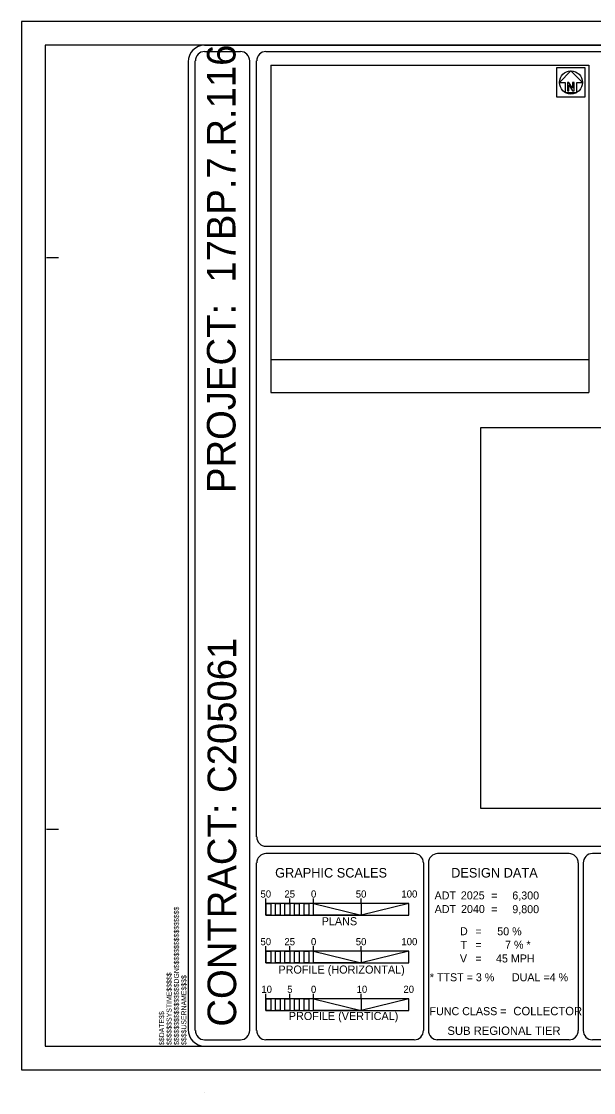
# Model space of a CAD drawing. Extents: x 2538775 to 2540487, y 826823 to 827953.
# Drawn here: x 2538775 to 2539375, y 826823 to 827947 of the extents above; entities that cross this region are included whole.
import ezdxf

# ---------------------------------------------------------------- set-up
doc = ezdxf.new("R2010")
doc.units = 0
for name, color, linetype in [('Old_Level_1', 7, 'Continuous'), ('Old_Level_10', 7, 'Continuous'), ('Old_Level_40', 7, 'Continuous'), ('Old_Level_41', 7, 'Continuous'), ('Old_Level_62', 7, 'Continuous'), ('Old_Level_63', 7, 'Continuous'), ('Sheet Data Field CELL', 7, 'Continuous')]:
    doc.layers.add(name, color=color, linetype=linetype)

msp = doc.modelspace()

# ---------------------------------------------------------------- linework, layer by layer
at = {"layer": 'Old_Level_1'}
msp.add_line((2538967, 826823.1), (2538967, 826823.1), dxfattribs=at)
msp.add_lwpolyline([(2539256.9, 827520.8), (2540207.7, 827520.8), (2540207.7, 827121.2), (2539256.9, 827121.2)], close=True, dxfattribs=at)
at = {"layer": 'Old_Level_10'}
for p, q in [((2539351.6, 827895.1), (2539339.6, 827882.8)), ((2539363.7, 827882.8), (2539351.6, 827895.1)), ((2539339.6, 827882.8), (2539345.6, 827882.8)), ((2539345.6, 827882.8), (2539345.6, 827872.2)), ((2539357.7, 827872.2), (2539357.7, 827882.8)), ((2539357.7, 827882.8), (2539363.7, 827882.8)), ((2539345.6, 827872.2), (2539357.7, 827872.2))]:
    msp.add_line(p, q, dxfattribs=at)
for points in [[(2539336.6, 827867.6), (2539366.7, 827867.6), (2539366.7, 827898.1), (2539336.6, 827898.1)], [(2539348, 827882.8), (2539348, 827874.2), (2539349.6, 827874.2), (2539349.6, 827880.2), (2539353.2, 827874.2), (2539354.9, 827874.2), (2539354.9, 827882.8), (2539353.2, 827882.8), (2539353.2, 827876.8), (2539349.6, 827882.8)]]:
    msp.add_lwpolyline(points, close=True, dxfattribs=at)
msp.add_ellipse((2539351.6, 827882.8), major_axis=(0, 12.2), ratio=0.985213, dxfattribs=at)
at = {"layer": 'Old_Level_40'}
for p, q in [((2538957.4, 827398.3), (2538957.4, 827905.4)), ((2539014.5, 827398.1), (2539014.5, 827905.4)), ((2539021.8, 827398.1), (2539021.8, 827905.4)), ((2539036.8, 827900.9), (2539370.3, 827900.9)), ((2539036.8, 827900.9), (2539036.8, 827557.5)), ((2539370.3, 827900.9), (2539370.3, 827557.5)), ((2539036.8, 827592), (2539370.3, 827592)), ((2539036.8, 827557.5), (2539370.3, 827557.5)), ((2538957.4, 826888.3), (2538957.4, 827398.3)), ((2539014.5, 826888.3), (2539014.5, 827398.1)), ((2539021.8, 827091.3), (2539021.8, 827398.1)), ((2540433.1, 827081.4), (2539031.5, 827081.4)), ((2539187.2, 827073.8), (2539031.5, 827073.8)), ((2539349.7, 827073.8), (2539211.7, 827073.8)), ((2539704.9, 827073.8), (2539374.2, 827073.8)), ((2539021.8, 826888.3), (2539021.8, 827064)), ((2539196.8, 827064), (2539196.8, 826888.3)), ((2539202, 827064), (2539202, 826888.3)), ((2539359.3, 827064), (2539359.3, 826888.3)), ((2539364.6, 827064), (2539364.6, 826888.3)), ((2539031.5, 827021.6), (2539031.5, 827026.6)), ((2539031.5, 827026.6), (2539031.5, 827026.6)), ((2539056.5, 827021.6), (2539056.5, 827026.6)), ((2539081.5, 827021.6), (2539081.5, 827026.6)), ((2539131.5, 827021.6), (2539131.5, 827026.6)), ((2539031.5, 827021.6), (2539031.5, 827009.1)), ((2539031.5, 827021.6), (2539031.5, 827021.6)), ((2539181.5, 827021.6), (2539031.5, 827021.6)), ((2539066.5, 827021.6), (2539066.5, 827009.1)), ((2539131.5, 827021.6), (2539131.5, 827009.1)), ((2539031.5, 827009.1), (2539181.5, 827009.1)), ((2539031.5, 826971.6), (2539031.5, 826976.6)), ((2539031.5, 826971.6), (2539031.5, 826976.6)), ((2539031.5, 826976.6), (2539031.5, 826976.6)), ((2539031.5, 826971.6), (2539031.5, 826959.1)), ((2539031.5, 826971.6), (2539031.5, 826971.6)), ((2539181.5, 826971.6), (2539031.5, 826971.6)), ((2539031.5, 826971.6), (2539031.5, 826971.6)), ((2539181.5, 826971.6), (2539031.5, 826971.6)), ((2539056.5, 826971.6), (2539056.5, 826976.6)), ((2539056.5, 826971.6), (2539056.5, 826976.6)), ((2539066.5, 826971.6), (2539066.5, 826959.1)), ((2539081.5, 826971.6), (2539081.5, 826976.6)), ((2539081.5, 826971.6), (2539081.5, 826976.6)), ((2539131.5, 826971.6), (2539131.5, 826976.6)), ((2539131.5, 826971.6), (2539131.5, 826976.6)), ((2539131.5, 826971.6), (2539131.5, 826959.1)), ((2539031.5, 826959.1), (2539181.5, 826959.1)), ((2539031.5, 826921.6), (2539031.5, 826926.6)), ((2539031.5, 826921.6), (2539031.5, 826926.6)), ((2539031.5, 826921.6), (2539031.5, 826926.6)), ((2539031.5, 826926.6), (2539031.5, 826926.6)), ((2539056.5, 826921.6), (2539056.5, 826926.6)), ((2539056.5, 826921.6), (2539056.5, 826926.6)), ((2539056.5, 826921.6), (2539056.5, 826926.6)), ((2539081.5, 826921.6), (2539081.5, 826926.6)), ((2539081.5, 826921.6), (2539081.5, 826926.6)), ((2539081.5, 826921.6), (2539081.5, 826926.6)), ((2539131.5, 826921.6), (2539131.5, 826926.6)), ((2539131.5, 826921.6), (2539131.5, 826926.6)), ((2539131.5, 826921.6), (2539131.5, 826926.6)), ((2539031.5, 826921.6), (2539031.5, 826909.1)), ((2539031.5, 826921.6), (2539031.5, 826921.6)), ((2539181.5, 826921.6), (2539031.5, 826921.6)), ((2539031.5, 826921.6), (2539031.5, 826921.6)), ((2539181.5, 826921.6), (2539031.5, 826921.6)), ((2539031.5, 826921.6), (2539031.5, 826921.6)), ((2539181.5, 826921.6), (2539031.5, 826921.6)), ((2539066.5, 826921.6), (2539066.5, 826909.1)), ((2539131.5, 826921.6), (2539131.5, 826909.1)), ((2539031.5, 826909.1), (2539181.5, 826909.1)), ((2538967.1, 826878.5), (2539004.8, 826878.5)), ((2539187.2, 826878.5), (2539031.5, 826878.5)), ((2539349.7, 826878.5), (2539210.8, 826878.5)), ((2539704.9, 826878.5), (2539374.2, 826878.5))]:
    msp.add_line(p, q, dxfattribs=at)
for points in [[(2538967.1, 827921.8), (2540432.7, 827921.8)], [(2538967.1, 827915.2), (2539004.8, 827915.2)], [(2539031.5, 827915.2), (2540433.1, 827915.2)], [(2538949.9, 827904.4), (2538949.9, 827398.3)], [(2538949.9, 827398.3), (2538949.9, 826889.3)], [(2538967.1, 826871.8), (2540432.7, 826871.8)]]:
    msp.add_lwpolyline(points, dxfattribs=at)
for points in [[(2539031.5, 827021.6), (2539036.5, 827021.6), (2539036.5, 827009.1), (2539031.5, 827009.1)], [(2539041.5, 827021.6), (2539046.5, 827021.6), (2539046.5, 827009.1), (2539041.5, 827009.1)], [(2539051.5, 827021.6), (2539056.5, 827021.6), (2539056.5, 827009.1), (2539051.5, 827009.1)], [(2539061.5, 827021.6), (2539066.5, 827021.6), (2539066.5, 827009.1), (2539061.5, 827009.1)], [(2539071.5, 827021.6), (2539076.5, 827021.6), (2539076.5, 827009.1), (2539071.5, 827009.1)], [(2539081.5, 827021.6), (2539131.5, 827009.1), (2539081.5, 827009.1)], [(2539181.5, 827021.6), (2539131.5, 827009.1), (2539181.5, 827009.1)], [(2539031.5, 826971.6), (2539036.5, 826971.6), (2539036.5, 826959.1), (2539031.5, 826959.1)], [(2539041.5, 826971.6), (2539046.5, 826971.6), (2539046.5, 826959.1), (2539041.5, 826959.1)], [(2539051.5, 826971.6), (2539056.5, 826971.6), (2539056.5, 826959.1), (2539051.5, 826959.1)], [(2539061.5, 826971.6), (2539066.5, 826971.6), (2539066.5, 826959.1), (2539061.5, 826959.1)], [(2539071.5, 826971.6), (2539076.5, 826971.6), (2539076.5, 826959.1), (2539071.5, 826959.1)], [(2539081.5, 826971.6), (2539131.5, 826959.1), (2539081.5, 826959.1)], [(2539181.5, 826971.6), (2539131.5, 826959.1), (2539181.5, 826959.1)], [(2539031.5, 826921.6), (2539036.5, 826921.6), (2539036.5, 826909.1), (2539031.5, 826909.1)], [(2539041.5, 826921.6), (2539046.5, 826921.6), (2539046.5, 826909.1), (2539041.5, 826909.1)], [(2539051.5, 826921.6), (2539056.5, 826921.6), (2539056.5, 826909.1), (2539051.5, 826909.1)], [(2539061.5, 826921.6), (2539066.5, 826921.6), (2539066.5, 826909.1), (2539061.5, 826909.1)], [(2539071.5, 826921.6), (2539076.5, 826921.6), (2539076.5, 826909.1), (2539071.5, 826909.1)], [(2539081.5, 826921.6), (2539131.5, 826909.1), (2539081.5, 826909.1)], [(2539181.5, 826921.6), (2539131.5, 826909.1), (2539181.5, 826909.1)]]:
    msp.add_lwpolyline(points, close=True, dxfattribs=at)
for centre, major_axis, start_param, end_param in [((2538967.1, 827904.4), (0, 17.5), 6.283183, 7.853978), ((2538967.1, 827905.4), (0, 9.81), 6.283183, 7.853978), ((2539004.8, 827905.4), (0, 9.81), 4.712408, 6.283194), ((2539031.5, 827905.4), (0, -9.81), 3.141603, 4.712391), ((2539031.5, 827091.3), (0, -9.81), 4.712389, 6.283185), ((2539031.5, 827064), (0, -9.81), 3.141593, 4.712389), ((2539031.5, 827064), (0, 9.81), 0, 1.570796), ((2539187.2, 827064), (0, 9.81), 4.712389, 6.283185), ((2539211.7, 827064), (0, -9.81), 3.141593, 4.712389), ((2539349.7, 827064), (0, 9.81), 4.712389, 6.283185), ((2539374.2, 827064), (0, -9.81), 3.140818, 4.712389), ((2538967.1, 826889.3), (0, -17.5), 4.712389, 6.283185), ((2538967.1, 826888.3), (0, -9.81), 4.712389, 6.283185), ((2539004.8, 826888.3), (0, 9.81), 3.141593, 4.712389), ((2539031.5, 826888.3), (0, -9.81), 4.712389, 6.283185), ((2539187.2, 826888.3), (0, -9.81), 0, 1.570796), ((2539211.7, 826888.3), (0, -9.81), 4.712389, 6.283185), ((2539349.7, 826888.3), (0, -9.81), 0, 1.570796), ((2539374.2, 826888.3), (0, -9.81), 4.712389, 6.283185)]:
    msp.add_ellipse(centre, major_axis=major_axis, ratio=0.985213, start_param=start_param, end_param=end_param, dxfattribs=at)
at = {"layer": 'Old_Level_41'}
for p, q in [((2538801.4, 827699.3), (2538813.9, 827699.3)), ((2538801.4, 827099.3), (2538813.9, 827099.3))]:
    msp.add_line(p, q, dxfattribs=at)
at = {"layer": 'Old_Level_62'}
msp.add_lwpolyline([(2538799.9, 826871.8), (2540449.9, 826871.8), (2540449.9, 827921.8), (2538799.9, 827921.8)], close=True, dxfattribs=at)
at = {"layer": 'Old_Level_63'}
msp.add_lwpolyline([(2538774.9, 826846.8), (2540474.9, 826846.8), (2540474.9, 827946.8), (2538774.9, 827946.8)], close=True, dxfattribs=at)

# ---------------------------------------------------------------- texts
at = {"layer": 'Old_Level_40'}
for s, height, rotation, p in [('PROJECT:  17BP.7.R.116', 30, 90, (2538999.6, 827452.1)), ('CONTRACT: C205061', 30, 90, (2539000.3, 826892.3)), ('GRAPHIC SCALES', 10, 360, (2539041.2, 827048.7)), ('DESIGN DATA', 10.023, 360, (2539225.9, 827048.7)), ('50', 7.5, 360, (2539025.8, 827027.7)), ('25', 7.5, 360, (2539050.9, 827027.7)), ('0', 7.5, 360, (2539078.8, 827027.7)), ('50', 7.5, 360, (2539125.8, 827027.7)), ('100', 7.5, 360, (2539173.7, 827027.7)), ('PLANS', 8.5, 360, (2539090, 826998.6)), ('50', 7.5, 360, (2539025.8, 826977.7)), ('25', 7.5, 360, (2539050.9, 826977.7)), ('0', 7.5, 360, (2539078.8, 826977.7)), ('0', 7.5, 360, (2539078.8, 826977.6)), ('50', 7.5, 360, (2539125.8, 826977.7)), ('100', 7.5, 360, (2539173.7, 826977.7)), ('PROFILE (HORIZONTAL)', 8.5, 360, (2539044.6, 826947.9)), ('10', 7.5, 360, (2539026.7, 826927.7)), ('5', 7.5, 360, (2539053.9, 826927.7)), ('0', 7.5, 360, (2539078.8, 826927.7)), ('0', 7.5, 360, (2539078.8, 826927.6)), ('0', 7.5, 360, (2539078.8, 826927.6)), ('10', 7.5, 360, (2539126.7, 826927.7)), ('20', 7.5, 360, (2539175.8, 826927.7)), ('COLLECTOR', 8.83, 360, (2539291.2, 826904.2)), ('PROFILE (VERTICAL)', 8.5, 360, (2539055.5, 826899.2)), ('SUB REGIONAL TIER', 8.83, 360, (2539222, 826883.6))]:
    msp.add_text(s, height=height, rotation=rotation, dxfattribs=at).set_placement(p)
at = {"layer": 'Old_Level_41'}
for s, p in [('$$$$$$$$$$$$$$$$DGN$$$$$$$$$$$$$$$$', (2538940.2, 826873)), ('$$$$$$SYSTIME$$$$$', (2538932.5, 826873)), ('$$$$USERNAME$$$$', (2538948, 826873)), ('$$DATE$$', (2538924.7, 826873))]:
    msp.add_text(s, height=5.25, rotation=90, dxfattribs=at).set_placement(p)
at = {"layer": 'Sheet Data Field CELL'}
for s, p in [('ADT', (2539208.5, 827025.7)), ('2025', (2539236.1, 827025.8)), ('=', (2539268, 827025.7)), ('6,300', (2539290.1, 827025.7)), ('ADT', (2539208.6, 827011.4)), ('2040', (2539236.3, 827011.5)), ('=', (2539268, 827011.3)), ('9,800', (2539290.1, 827011.3)), ('D', (2539235.2, 826988.2)), ('=', (2539251.4, 826988.1)), ('50 %', (2539274.3, 826988.1)), ('T', (2539235.8, 826973.9)), ('=', (2539251.4, 826974)), ('7 % *', (2539282.5, 826974)), ('V', (2539235.1, 826959.6)), ('=', (2539251.4, 826959.6)), ('45 MPH', (2539273, 826959.6)), ('* TTST = 3 %', (2539203.5, 826939.9)), ('DUAL =4 %', (2539289.7, 826939.9)), ('FUNC CLASS =', (2539203.2, 826904.3))]:
    msp.add_text(s, height=8.4, rotation=0, dxfattribs=at).set_placement(p)

doc.saveas('drawing.dxf')
